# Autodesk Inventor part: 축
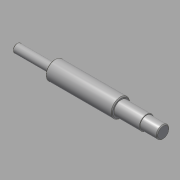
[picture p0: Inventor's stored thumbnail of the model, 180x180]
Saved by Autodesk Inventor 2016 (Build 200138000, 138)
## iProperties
Created: 2016-05
Part Number: 축
Document SubType Name: Modeling
Designer: mduedu
Density: 7.86 g/cm^3
Material: 강철, 연강
Appearance: 강철
Author: mduedu
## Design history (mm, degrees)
sketch "스케치1"
  geometry: L1 (-42, 11)-(-42, 5); L2 (37, 11)-(37, 8.5); L3 (-87, 0)-(87, 0); L4 (-42, 11)-(37, 11); L5 (37, 11)-(37, 8.5); L6 (-42, 11)-(-42, 5); L7 (-42, 5)-(-87, 5); L8 (-87, 5)-(-87, 0); L9 (37, 8.5)-(67, 8.5); L10 (87, 7.5)-(87, 0); L11 (67, 8.5)-(67, 7.5); L12 (67, 7.5)-(87, 7.5); 1 further point
  constraints: 24 end point, 9 perpendicular, 2 midpoint, 1 horizontal
  dimensions: "d0" = 22 diameter of L4 L3; "d1" = 10 diameter of L7 L3; "d2" = 45 distance between parallel lines of L8 L1; "d3" = 50 distance between parallel lines of L10 L2; "d4" = 15 diameter of L12 L3; "d5" = 20 distance between parallel lines of L10 L11; "d29" = 79 distance of L1.start L2.start; "d37" = 17 diameter of L9 L3
revolve "회전1" stored, may be unused: angle "d6" = 90 deg
chamfer "모따기2" distance "d32" = 1; stored, may be unused: second distance "d33" = 2, angle "d34" = 45 deg
node "작업 평면4"
sketch "스케치4"
  geometry: L1 (-5, 2.5)-(5, 2.5); L2 (5, -2.5)-(-5, -2.5); L3 (-10, -6.5)-(-10, 6.5) reference; A1 r 2.5 centre (5, 0) between (5, -2.5) and (5, 2.5); A2 r 2.5 centre (-5, 0) between (-5, 2.5) and (-5, -2.5); 1 further point
  constraints: 4 end point, 4 point on circle, 4 tangent, 2 centre point, 1 horizontal, 1 horizontal alignment, 1 parallel
  dimensions: "d20" = 5 distance between parallel lines of L2 L1; "d21" = 15 dimension on A1 A2; "d35" = 2.5 distance edge to line of A2 L3
extrude "돌출3" cut sketch "스케치4" distance "d23" = 3; taper "d24" = 0 deg
node "작업 평면5"
sketch "스케치5"
  geometry: L1 (22.5, 1.5)-(10, 1.5); L2 (10, -1.5)-(22.5, -1.5); L3 (22.5, 4)-(22.5, -4) reference; A1 r 1.5 centre (10, 0) between (10, 1.5) and (10, -1.5); 3 further points
  constraints: 4 end point, 2 horizontal alignment, 2 point on circle, 2 point on line, 2 tangent, 1 centre point, 1 coincident, 1 horizontal, 1 midpoint
  dimensions: "d25" = 3 distance between parallel lines of L2 L1; "d36" = 14 dimension on A1 L3
extrude "돌출4" cut sketch "스케치5" distance "d27" = 1.8; taper "d28" = 0 deg
node "솔리드1"
